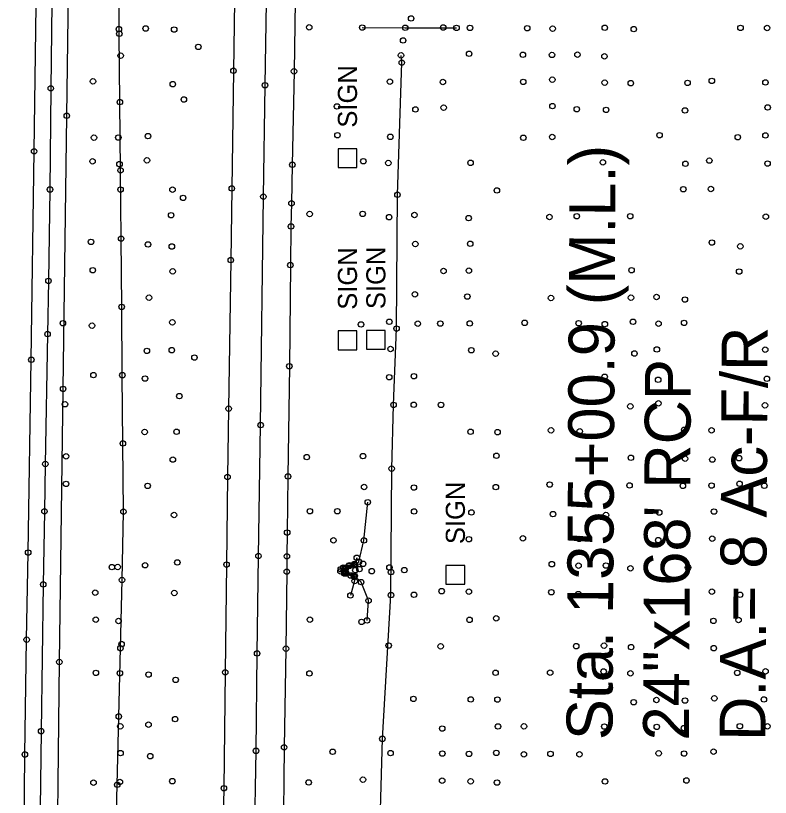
# Model space of a CAD drawing. Extents: x 20503438 to 20508873, y 7964251 to 7984667.
# Drawn here: x 20506610 to 20506886.2, y 7968218.3 to 7968504.5 of the extents above; entities that cross this region are included whole.
import ezdxf

# ---------------------------------------------------------------- set-up
doc = ezdxf.new("R2010")
doc.units = 0
for name, color, linetype in [('SurBreakLine', 7, 'Continuous'), ('SurConcreteSlab', 7, 'Continuous'), ('SurDikeDam', 7, 'Continuous'), ('SurDrainageArrowDown', 7, 'Continuous'), ('SurDrainageArrowUp', 7, 'Continuous'), ('SurEdgeRoadPaved', 7, 'Continuous'), ('SurEdgeShoulderPaved', 7, 'Continuous'), ('SurGuardRailCable', 7, 'Continuous'), ('SurPointsNonDTM', 7, 'Continuous'), ('SurRoadPoints', 7, 'Continuous'), ('SurSurveyPoints', 7, 'Continuous'), ('SurTxtDrainage', 7, 'Continuous')]:
    doc.layers.add(name, color=color, linetype=linetype)

msp = doc.modelspace()

# ---------------------------------------------------------------- linework, layer by layer
at = {"layer": 'SurBreakLine'}
for points in [[(20506690.26, 7968518.48), (20506689.75, 7968484.33), (20506689.14, 7968441.26), (20506688.76, 7968414.99), (20506687.98, 7968360.62), (20506687.56, 7968335.59), (20506687.22, 7968303.54), (20506686.72, 7968264.08), (20506686.24, 7968221.64), (20506686.02, 7968210.16), (20506685.58, 7968184.12), (20506684.98, 7968126.76), (20506684.47, 7968088.01), (20506683.95, 7968050.04), (20506683.85, 7968029.76), (20506683.42, 7967981.38), (20506682.3, 7967907.93)], [(20506734.26, 7968303.36), (20506735.63, 7968304.56), (20506737.46, 7968312.37), (20506738.9, 7968326.34)], [(20506734.89, 7968306.02), (20506733.99, 7968303.68), (20506732.17, 7968303.3), (20506729.95, 7968302.43), (20506729.03, 7968301.82), (20506728.91, 7968301.03), (20506730.35, 7968300.23), (20506733.92, 7968298.99), (20506734.08, 7968297.52), (20506732.55, 7968292.22)], [(20506738.63, 7968283.08), (20506739.18, 7968290.33), (20506736.44, 7968297.1), (20506734.08, 7968299.39)]]:
    msp.add_lwpolyline(points, dxfattribs=at)
at = {"layer": 'SurConcreteSlab'}
msp.add_lwpolyline([(20506712.33, 7968509.69), (20506711.9, 7968484.13), (20506711.28, 7968449.91), (20506710.98, 7968435.8), (20506710.8, 7968427.34), (20506710.57, 7968413.18), (20506710.2, 7968376.16), (20506709.68, 7968335.8), (20506709.4, 7968315.24), (20506709.29, 7968306.55), (20506709.24, 7968300.91), (20506708.97, 7968272.73), (20506708.28, 7968236.62), (20506707.97, 7968201.29), (20506707.58, 7968176.03), (20506706.92, 7968128.82), (20506706.72, 7968095.09), (20506706.2, 7968052.89), (20506705.8, 7968026.3), (20506705.46, 7967997.77), (20506705.09, 7967952.19), (20506704.42, 7967914.18)], dxfattribs=at)
msp.add_lwpolyline([(20506733.89, 7968299.39), (20506730.94, 7968300.52), (20506730.53, 7968301.1), (20506730.49, 7968301.76), (20506730.95, 7968302.33), (20506734.13, 7968303.33), (20506733.94, 7968303.54), (20506732.17, 7968303.03), (20506730.71, 7968302.42), (20506730.38, 7968301.77), (20506730.31, 7968300.93), (20506730.91, 7968300.25), (20506732.65, 7968299.52), (20506734, 7968299.1)], close=True, dxfattribs=at)
at = {"layer": 'SurDikeDam'}
msp.add_lwpolyline([(20506736.86, 7968500.15), (20506752.59, 7968500.08), (20506771.36, 7968500.04)], dxfattribs=at)
at = {"layer": 'SurDrainageArrowDown'}
msp.add_lwpolyline([(20506646.61, 7968197.92), (20506647.2, 7968222.91), (20506647.79, 7968247.9), (20506648.38, 7968272.89), (20506648.97, 7968297.89), (20506649.5, 7968322.88), (20506649.28, 7968347.88), (20506649.07, 7968372.88), (20506648.85, 7968397.88), (20506648.63, 7968422.88), (20506648.42, 7968447.87), (20506648.2, 7968472.87), (20506647.98, 7968497.87), (20506647.77, 7968522.87)], dxfattribs=at)
at = {"layer": 'SurDrainageArrowUp'}
msp.add_lwpolyline([(20506738, 7967924.5), (20506738.23, 7967987.24), (20506737.97, 7968040.14), (20506739.42, 7968087.08), (20506741.75, 7968143.37), (20506742.94, 7968192.11), (20506744.24, 7968239.72), (20506747.37, 7968292.34), (20506747.64, 7968338.63), (20506748.32, 7968361.98), (20506749.44, 7968389.93), (20506749.76, 7968438.94), (20506751.33, 7968487.3), (20506751.06, 7968489.97)], dxfattribs=at)
at = {"layer": 'SurEdgeRoadPaved'}
for points in [[(20506610.04, 7967919.68), (20506610.47, 7967953.23), (20506610.95, 7967990.8), (20506611.57, 7968036.16), (20506611.86, 7968062.36), (20506612.31, 7968104.23), (20506612.6, 7968130.7), (20506612.95, 7968165.62), (20506613.14, 7968206.99), (20506613.43, 7968233.98), (20506614.06, 7968276.04), (20506614.62, 7968307.91), (20506615.76, 7968378.52), (20506616.8, 7968454.85), (20506618.19, 7968552.78)], [(20506686.56, 7967334.59), (20506686.95, 7967373.78), (20506689.55, 7967556.46), (20506690.33, 7967629.33), (20506692, 7967750.22), (20506692.37, 7967781.34), (20506692.82, 7967818.08), (20506693.38, 7967854.94), (20506693.74, 7967887.88), (20506694.06, 7967917.79), (20506694.67, 7967952.73), (20506695.11, 7967987.1), (20506695.52, 7968027.63), (20506696.58, 7968118.81), (20506697.03, 7968160.54), (20506697.41, 7968201.34), (20506698.01, 7968235.32), (20506698.41, 7968270.98), (20506698.89, 7968306.65), (20506699.7, 7968354.59), (20506700.7, 7968438.24), (20506701.3, 7968479.04), (20506702.09, 7968524.73)]]:
    msp.add_lwpolyline(points, dxfattribs=at)
at = {"layer": 'SurEdgeShoulderPaved'}
msp.add_lwpolyline([(20506624.07, 7968571.84), (20506622.9, 7968477.89), (20506622.6, 7968440.86), (20506622.03, 7968407.41), (20506621.73, 7968387.9), (20506620.89, 7968340.34), (20506620.58, 7968323), (20506620.12, 7968296.25), (20506619.36, 7968242.53), (20506618.92, 7968204.96), (20506618.76, 7968185.33), (20506618.47, 7968142.62), (20506617.98, 7968093.95), (20506617.79, 7968073.85), (20506617.43, 7968040.86), (20506616.93, 7968010.09), (20506616.58, 7967973.81), (20506616.23, 7967954.34), (20506615.93, 7967937.65), (20506615.89, 7967920.93)], dxfattribs=at)
at = {"layer": 'SurGuardRailCable'}
msp.add_lwpolyline([(20506615.02, 7967359.71), (20506615.99, 7967430.36), (20506617.34, 7967530.35), (20506618.65, 7967630.34), (20506619.88, 7967727.43), (20506620.83, 7967791.42), (20506621.77, 7967855.41), (20506622.47, 7967921.12), (20506623.1, 7967987.28), (20506623.9, 7968067.87), (20506624.93, 7968167.87), (20506626.04, 7968267.86), (20506627.42, 7968367.85), (20506628.76, 7968467.84), (20506630.09, 7968567.83)], dxfattribs=at)
at = {"layer": 'SurPointsNonDTM'}
for centre in [(20506628.76, 7968467.84), (20506627.42, 7968367.85), (20506645.25, 7968302.61), (20506626.04, 7968267.86)]:
    msp.add_circle(centre, 1, dxfattribs=at)
at = {"layer": 'SurRoadPoints'}
for points in [[(20506734.89, 7968452.3), (20506734.89, 7968452.3), (20506734.89, 7968455.73), (20506728.03, 7968455.73), (20506728.03, 7968448.87), (20506734.89, 7968448.87), (20506734.89, 7968452.3)], [(20506734.89, 7968385.62), (20506734.89, 7968385.62), (20506734.89, 7968389.05), (20506728.03, 7968389.05), (20506728.03, 7968382.19), (20506734.89, 7968382.19), (20506734.89, 7968385.62)], [(20506745.28, 7968385.85), (20506745.28, 7968385.85), (20506745.28, 7968389.28), (20506738.42, 7968389.28), (20506738.42, 7968382.42), (20506745.28, 7968382.42), (20506745.28, 7968385.85)], [(20506774.37, 7968299.81), (20506774.37, 7968299.81), (20506774.37, 7968303.24), (20506767.51, 7968303.24), (20506767.51, 7968296.38), (20506774.37, 7968296.38), (20506774.37, 7968299.81)]]:
    msp.add_lwpolyline(points, dxfattribs=at)
at = {"layer": 'SurSurveyPoints'}
for centre in [(20506754.74, 7968503.48), (20506647.82, 7968499.59), (20506657.6, 7968499.81), (20506668.05, 7968499.43), (20506717.46, 7968500.25), (20506736.86, 7968500.15), (20506752.59, 7968500.08), (20506766.5, 7968500.17), (20506771.36, 7968500.04), (20506776.28, 7968500.03), (20506797.23, 7968499.9), (20506806.54, 7968499.73), (20506825.61, 7968500.06), (20506836.23, 7968499.58), (20506875.29, 7968500.04), (20506885.01, 7968500.01), (20506647.98, 7968497.87), (20506676.88, 7968493.09), (20506751.83, 7968495.43), (20506775.98, 7968490.56), (20506648.45, 7968489.88), (20506751.06, 7968489.97), (20506795.67, 7968490.18), (20506806.29, 7968490.13), (20506815.63, 7968490.22), (20506825.51, 7968489.61), (20506751.33, 7968487.3), (20506689.75, 7968484.33), (20506711.9, 7968484.13), (20506638.33, 7968480.45), (20506667.53, 7968479.43), (20506701.3, 7968479.04), (20506746.99, 7968480.35), (20506766.37, 7968480.22), (20506795.78, 7968480.27), (20506806.41, 7968481.09), (20506825.58, 7968479.96), (20506835.14, 7968479.79), (20506855.91, 7968479.9), (20506864.79, 7968480.62), (20506884.4, 7968480.05), (20506622.9, 7968477.89), (20506671.61, 7968473.81), (20506648.2, 7968472.87), (20506727.61, 7968471.27), (20506766.65, 7968470.82), (20506806.48, 7968471.38), (20506815.36, 7968470.26), (20506885.21, 7968470.89), (20506756.35, 7968470.17), (20506826.12, 7968470.02), (20506854.96, 7968469.8), (20506638.69, 7968459.85), (20506647.6, 7968459.89), (20506658.45, 7968460.41), (20506727.79, 7968460.73), (20506747.17, 7968460.14), (20506795.82, 7968459.8), (20506806.38, 7968460.1), (20506845.67, 7968460.72), (20506874.28, 7968460.01), (20506884.41, 7968460.65), (20506616.8, 7968454.85), (20506638.2, 7968451.17), (20506658.09, 7968451.53), (20506737.25, 7968451.22), (20506746.41, 7968450.58), (20506776.52, 7968450.62), (20506824.92, 7968450.8), (20506855.13, 7968450.29), (20506863.88, 7968451.44), (20506885.19, 7968450.37), (20506648.05, 7968450.14), (20506648.42, 7968447.87), (20506711.28, 7968449.91), (20506622.6, 7968440.86), (20506648.42, 7968440.83), (20506667.44, 7968440.78), (20506689.14, 7968441.26), (20506749.76, 7968438.94), (20506786.14, 7968440.5), (20506854.36, 7968440.97), (20506864.45, 7968441.04), (20506671.31, 7968437.78), (20506700.7, 7968438.24), (20506710.98, 7968435.8), (20506666.92, 7968431.45), (20506717.63, 7968431.9), (20506737.01, 7968431.93), (20506746.71, 7968430.73), (20506755.97, 7968431.53), (20506775.8, 7968430.38), (20506805.36, 7968430.8), (20506815.36, 7968431.07), (20506834.92, 7968431.07), (20506884.55, 7968430.91), (20506710.8, 7968427.34), (20506637.6, 7968421.68), (20506648.63, 7968422.88), (20506658.48, 7968420.73), (20506667.2, 7968419.99), (20506756.32, 7968420.91), (20506776.37, 7968420.98), (20506864.83, 7968421.44), (20506875.22, 7968420.06), (20506688.76, 7968414.99), (20506710.57, 7968413.18), (20506638.26, 7968411.29), (20506667.51, 7968410.91), (20506766.64, 7968411.02), (20506775.9, 7968411.15), (20506835.42, 7968411.31), (20506874.8, 7968410.82), (20506622.03, 7968407.41), (20506756.13, 7968402.49), (20506775.32, 7968401.67), (20506844.56, 7968401.51), (20506658.86, 7968401.23), (20506805.94, 7968401.12), (20506835.21, 7968401.25), (20506854.94, 7968400.55), (20506648.85, 7968397.88), (20506627.32, 7968391.9), (20506638, 7968391.02), (20506667.39, 7968392.24), (20506736.42, 7968391.46), (20506746.78, 7968392.43), (20506757.18, 7968391.71), (20506765.46, 7968391.76), (20506776.23, 7968391.8), (20506796.32, 7968392.04), (20506816.06, 7968391.89), (20506825.64, 7968391.56), (20506835.97, 7968392.43), (20506845.31, 7968391.73), (20506854.66, 7968392.01), (20506621.73, 7968387.9), (20506749.44, 7968389.93), (20506658.07, 7968381.76), (20506667.17, 7968382.03), (20506747.24, 7968382.48), (20506776.77, 7968382.01), (20506844.67, 7968382.29), (20506884.32, 7968382.23), (20506675.48, 7968379.32), (20506785.67, 7968380.77), (20506836.48, 7968380.81), (20506615.76, 7968378.52), (20506710.2, 7968376.16), (20506638.52, 7968372.89), (20506649.07, 7968372.88), (20506657.38, 7968371.64), (20506746.73, 7968372.11), (20506755.76, 7968372.49), (20506825.57, 7968372.3), (20506845.15, 7968371.2), (20506884.93, 7968371.54), (20506669.96, 7968365.21), (20506628.12, 7968362.22), (20506748.32, 7968361.98), (20506755.73, 7968362.03), (20506765.67, 7968362), (20506834.97, 7968361.47), (20506845.25, 7968362.58), (20506884.23, 7968361.85), (20506687.98, 7968360.62), (20506699.7, 7968354.59), (20506854.69, 7968352.88), (20506657.24, 7968352.05), (20506668.92, 7968352.14), (20506776.51, 7968352.14), (20506786.39, 7968352.01), (20506805.96, 7968352.69), (20506816.47, 7968352.29), (20506864.68, 7968352.69), (20506649.28, 7968347.88), (20506628.51, 7968343.16), (20506667.56, 7968341.96), (20506716.57, 7968342.88), (20506737.13, 7968343.23), (20506785.97, 7968343.36), (20506835.18, 7968342.62), (20506855, 7968342.29), (20506864.99, 7968341.96), (20506874.74, 7968342.48), (20506620.89, 7968340.34), (20506747.64, 7968338.63), (20506709.68, 7968335.8), (20506628.49, 7968333.08), (20506687.56, 7968335.59), (20506805.45, 7968332.82), (20506874.94, 7968333.11), (20506658.35, 7968332.34), (20506737.55, 7968331.91), (20506755.77, 7968331.71), (20506785.76, 7968331.9), (20506834.68, 7968332.49), (20506854.21, 7968332.35), (20506864.69, 7968332.47), (20506883.99, 7968332.37), (20506738.9, 7968326.34), (20506620.58, 7968323), (20506649.5, 7968322.88), (20506668.01, 7968321.66), (20506717.71, 7968323.06), (20506727.76, 7968323.07), (20506755.86, 7968322.98), (20506776.84, 7968322.62), (20506806.67, 7968321.99), (20506826.05, 7968321.66), (20506845.55, 7968322.59), (20506865.58, 7968322.93), (20506709.4, 7968315.24), (20506775.9, 7968312.81), (20506795.65, 7968313.14), (20506816.26, 7968312.94), (20506864.94, 7968313.03), (20506726.34, 7968312.38), (20506737.46, 7968312.37), (20506845.19, 7968312.48), (20506614.62, 7968307.91), (20506669.2, 7968304.31), (20506698.89, 7968306.65), (20506709.29, 7968306.55), (20506734.89, 7968306.02), (20506735.63, 7968304.56), (20506647.39, 7968302.64), (20506657.42, 7968303.27), (20506687.22, 7968303.54), (20506729.03, 7968301.82), (20506729.95, 7968302.43), (20506730.38, 7968301.77), (20506730.49, 7968301.76), (20506730.71, 7968302.42), (20506730.95, 7968302.33), (20506732.17, 7968303.3), (20506732.17, 7968303.03), (20506733.94, 7968303.54), (20506733.99, 7968303.68), (20506734.13, 7968303.33), (20506734.26, 7968303.36), (20506734.33, 7968301.49), (20506735.84, 7968301.85), (20506737.2, 7968303.79), (20506746.83, 7968302.45), (20506752.27, 7968301.49), (20506806.24, 7968303.67), (20506816.04, 7968303.13), (20506826.06, 7968303.15), (20506835, 7968302.14), (20506856.08, 7968302.46), (20506709.24, 7968300.91), (20506728.91, 7968301.03), (20506730.31, 7968300.93), (20506730.35, 7968300.23), (20506730.53, 7968301.1), (20506730.91, 7968300.25), (20506730.94, 7968300.52), (20506732.65, 7968299.52), (20506733.89, 7968299.39), (20506733.92, 7968298.99), (20506734, 7968299.1), (20506734.08, 7968299.39), (20506740.37, 7968301.11), (20506747.38, 7968300.77), (20506620.12, 7968296.25), (20506648.97, 7968297.89), (20506734.08, 7968297.52), (20506736.44, 7968297.1), (20506639.16, 7968293.26), (20506668.1, 7968293.11), (20506765.91, 7968293.79), (20506775.9, 7968293.61), (20506806.07, 7968293.4), (20506864.83, 7968293.6), (20506732.55, 7968292.22), (20506739.18, 7968290.33), (20506747.37, 7968292.34), (20506755.79, 7968292.46), (20506815.96, 7968292.69), (20506875.13, 7968292.45), (20506639.35, 7968283.33), (20506647.7, 7968282.85), (20506717.72, 7968283.36), (20506736.61, 7968282.54), (20506738.63, 7968283.08), (20506776.15, 7968283.29), (20506785.89, 7968283.86), (20506865.37, 7968282.91), (20506874.57, 7968283.24), (20506614.06, 7968276.04), (20506648.38, 7968272.89), (20506648.79, 7968274.41), (20506708.97, 7968272.73), (20506746.56, 7968273.86), (20506765.56, 7968273.59), (20506815.16, 7968273.65), (20506825.34, 7968273.85), (20506835.25, 7968273.29), (20506865.51, 7968272.91), (20506698.41, 7968270.98), (20506825.19, 7968264.39), (20506884.44, 7968264.42), (20506639.41, 7968263.87), (20506648.18, 7968263.73), (20506658.67, 7968263.24), (20506668.58, 7968261.31), (20506686.72, 7968264.08), (20506717.54, 7968263.67), (20506785.66, 7968263.91), (20506805.63, 7968263.95), (20506835.01, 7968263.68), (20506874.1, 7968263.87), (20506755.6, 7968254.33), (20506776.59, 7968254.14), (20506786.33, 7968254.11), (20506836.2, 7968253.13), (20506844.51, 7968253.96), (20506854.99, 7968253.74), (20506865.71, 7968254.53), (20506883.83, 7968254.15), (20506647.79, 7968247.9), (20506668.4, 7968246.93), (20506648.34, 7968244.31), (20506658.65, 7968244.91), (20506786.54, 7968244.25), (20506796.06, 7968244.28), (20506825.46, 7968244.2), (20506844.64, 7968244.08), (20506875.04, 7968244.32), (20506885.14, 7968244.31), (20506619.36, 7968242.53), (20506766.15, 7968243.49), (20506854.59, 7968243.65), (20506744.24, 7968239.72), (20506708.28, 7968236.62), (20506613.43, 7968233.98), (20506648.44, 7968234.48), (20506659.3, 7968233.37), (20506698.01, 7968235.32), (20506726.03, 7968234.99), (20506747.22, 7968234.5), (20506766.19, 7968234.32), (20506775.94, 7968234.2), (20506785.92, 7968234.58), (20506796.03, 7968234.06), (20506805.76, 7968234.19), (20506816.35, 7968234.05), (20506845.35, 7968234.39), (20506854.64, 7968234.34), (20506865.43, 7968235), (20506667.38, 7968224.22), (20506737.14, 7968224.78), (20506766.11, 7968224.39), (20506776.53, 7968224.17), (20506825.71, 7968224.13), (20506855.51, 7968224.46), (20506638.53, 7968223.67), (20506647.2, 7968222.91), (20506648.16, 7968223.89), (20506686.24, 7968221.64), (20506717.27, 7968223.76), (20506786.19, 7968223.71)]:
    msp.add_circle(centre, 1, dxfattribs=at)

# ---------------------------------------------------------------- texts
at = {"layer": 'SurRoadPoints'}
for p in [(20506734.96, 7968463.51), (20506734.96, 7968396.83), (20506745.35, 7968397.06), (20506774.44, 7968311.02)]:
    msp.add_text('SIGN', height=6.995, rotation=90, dxfattribs=at).set_placement(p)
at = {"layer": 'SurTxtDrainage'}
for s, p in [('Sta. 1355+00.9 (M.L.)', (20506828.41, 7968239.22)), ('D.A.= 8 Ac-F/R', (20506884.41, 7968238.92)), ('24"x168\' RCP', (20506856.41, 7968239.07))]:
    msp.add_text(s, height=16.8, rotation=89.6917, dxfattribs=at).set_placement(p)

doc.saveas('drawing.dxf')
